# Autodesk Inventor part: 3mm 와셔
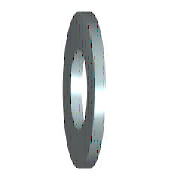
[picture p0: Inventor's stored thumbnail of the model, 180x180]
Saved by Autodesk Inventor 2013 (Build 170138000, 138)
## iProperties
Created: 2012-02
Part Number: 3mm 와셔
Material: 스테인리스강
Description: 평면 와셔 - 대형 시리즈 - 제품 등급 A
Document SubType Name: Modeling
Standard: ISO 7093 A
Designer: mduedu
Standard Revision: First Edition 2000-06-01
Standards Organization: ISO
Language: ko-KR
Size Designation: ST 3 - 140 HV - A
Categories: <MemberInstance><Categories><Category DisplayName="조임쇠" InternalName="e4da775c-781d-43d5-af7c-5136215cf5a6" Mnemonic="FSTN"><Category DisplayName="와셔" InternalN
Density: 8.08 g/cm^3
Mass: 0.359235 g
Surface Area: 1.41811 cm^2
Volume: 0.0444598 cm^3
IsCustomPart: 1
Author: mduedu
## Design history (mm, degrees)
sketch "스케치"
  geometry: C1 r 4.5 at (0, 0); C2 r 1.6 at (0, 0); 1 further point
  constraints: 2 centre point, 2 coincident
  dimensions: "d0" = 3.2 diameter of C2 (= SD1); "d1" = 9 diameter of C1 (= SD2)
extrude "본체" new body sketch "스케치" distance "d2" = 0.8 (= SD); taper "d3" = 0 deg
workaxis "Work Axis1"
workplane "Work Plane1"
sketch "스케치5"
  geometry: 2 further points
  constraints: 1 coincident
body "Solid1"
other parameters: "SD1" = 3.2 [user parameter; used in 1 equation term], "SD2" = 9 [user parameter; used in 1 equation term], "SD" = 0.8 [user parameter; used in 1 equation term], "d4" = 0, "d5" = 0, "d6" = 0, "d7" = 0, "NND" = 3 [user parameter]
